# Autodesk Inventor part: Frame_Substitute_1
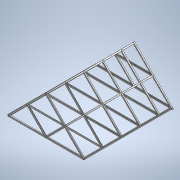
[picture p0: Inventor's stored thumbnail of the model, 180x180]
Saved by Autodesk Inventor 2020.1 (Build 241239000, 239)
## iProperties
Created: 2019-10
Part Number: Frame_Substitute_1
Material: Generic
Document SubType Name: Modeling
Designer: Synergysoft Dell02
Density: 1 g/cm^3
Appearance: Default
Author: Synergysoft Dell02
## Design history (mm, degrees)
derived "Frame.iam"
body "Solid1"
node "Frame 1572343187933.iam:1::ISO 100x100x4:1"
node "Frame 1572343187933.iam:1::ISO 100x100x4:2"
body "Solid2"
node "Frame 1572343187933.iam:1::ISO 100x100x4:3"
body "Solid3"
node "Frame 1572343187933.iam:1::ISO 100x100x4:4"
body "Solid4"
node "Frame 1572343187933.iam:1::ISO 100x100x4:5"
body "Solid5"
node "Frame 1572343187933.iam:1::ISO 100x100x4:6"
body "Solid6"
node "Frame 1572343187933.iam:1::ISO 100x100x4:7"
body "Solid7"
node "Frame 1572343187933.iam:1::ISO 100x100x4:8"
body "Solid8"
node "Frame 1572343187933.iam:1::ISO 100x100x4:9"
body "Solid9"
node "Frame 1572343187933.iam:1::ISO 100x100x4:10"
body "Solid10"
node "Frame 1572343187933.iam:1::ISO 100x100x4:11"
body "Solid11"
node "Frame 1572343187933.iam:1::ISO 100x100x4:12"
body "Solid12"
node "Frame 1572343187933.iam:1::ISO 100x100x4:13"
body "Solid13"
node "Frame 1572343187933.iam:1::ISO 100x100x4:14"
body "Solid14"
node "Frame 1572343187933.iam:1::ISO 100x100x4:15"
body "Solid15"
node "Frame 1572343187933.iam:1::ISO 100x100x4:16"
body "Solid16"
node "Frame 1572343187933.iam:1::ISO 100x100x4:17"
body "Solid17"
node "Frame 1572343187933.iam:1::ISO 100x100x4:18"
body "Solid18"
node "Frame 1572343187933.iam:1::ISO 100x100x4:19"
body "Solid19"
node "Frame 1572343187933.iam:1::ISO 100x100x4:20"
body "Solid20"
node "Frame 1572343187933.iam:1::ISO 100x100x4:21"
body "Solid21"
node "Frame 1572343187933.iam:1::ISO 100x100x4:22"
body "Solid22"
node "Frame 1572343187933.iam:1::ISO 100x100x4:23"
body "Solid23"
node "Frame 1572343187933.iam:1::ISO 100x100x4:24"
body "Solid24"
node "Frame 1572343187933.iam:1::ISO 100x100x4:25"
body "Solid25"
node "Frame 1572343187933.iam:1::ISO 100x100x4:26"
body "Solid26"
node "Frame 1572343187933.iam:1::ISO 100x100x4:27"
body "Solid27"
node "Frame 1572343187933.iam:1::ISO 100x100x4:28"
body "Solid28"
node "Frame 1572343187933.iam:1::ISO 100x100x4:29"
body "Solid29"
